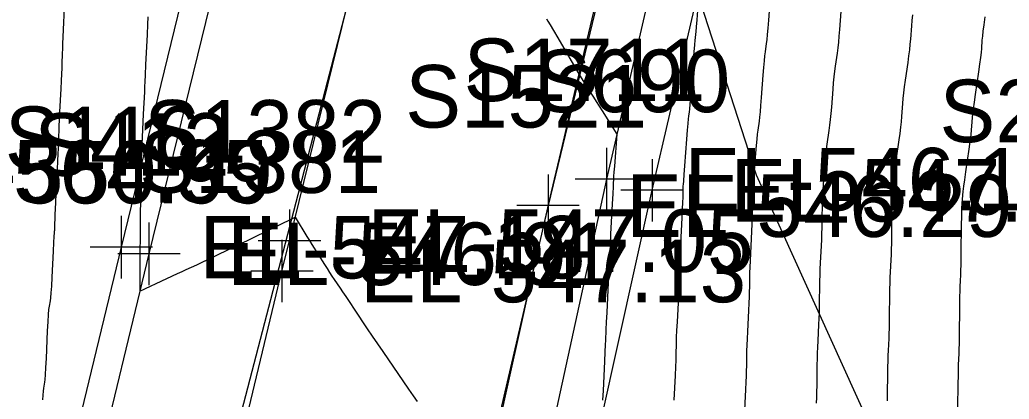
# Model space of a CAD drawing. Extents: x 1724534 to 1727318, y 657156 to 660047.
# Drawn here: x 1725468.1 to 1725531.4, y 659119.9 to 659144.2 of the extents above; entities that cross this region are included whole.
import ezdxf

# ---------------------------------------------------------------- set-up
doc = ezdxf.new("R2010")
doc.units = 0
for name, color, linetype in [('SURVEY - CENTERLINE - Preliminary', 7, 'Continuous'), ('SURVEY - CONTOURS - Index with Text', 7, 'Continuous'), ('SURVEY - CONTOURS - Intermediate with optional Text', 7, 'Continuous'), ('SURVEY - DRAINAGE - Area Shapes', 7, 'Continuous'), ('SURVEY - DTM - Breaklines', 7, 'Continuous'), ('SURVEY - DTM - Breaklines - Points - Elevations', 7, 'Continuous'), ('SURVEY - DTM - Breaklines - Points - Locators', 7, 'Continuous'), ('SURVEY - DTM - Breaklines - Points - Numbers', 7, 'Continuous'), ('SURVEY - NON-TRANSPORTATION - Features - Points - Elevations', 7, 'Continuous'), ('SURVEY - ROADSIDE BARRIERS - Points - Elevations', 7, 'Continuous'), ('SURVEY - ROADSIDE BARRIERS - Points - Locators', 7, 'Continuous'), ('SURVEY - ROADSIDE BARRIERS - Points - Numbers', 7, 'Continuous'), ('SURVEY - ROADSIDE BARRIERS with Text', 7, 'Continuous'), ('SURVEY - TRANSPORTATION - Features', 7, 'Continuous'), ('SURVEY - TRANSPORTATION - Features - Points - Elevations', 7, 'Continuous'), ('SURVEY - TRANSPORTATION - Features - Points - Locators', 7, 'Continuous'), ('SURVEY - TRANSPORTATION - Features - Points - Numbers', 7, 'Continuous'), ('SURVEY - TRANSPORTATION - Roads', 7, 'Continuous'), ('SURVEY - TRANSPORTATION - Roads - Points - Elevations', 7, 'Continuous'), ('SURVEY - TRANSPORTATION - Roads - Points - Locators', 7, 'Continuous'), ('SURVEY - TRANSPORTATION - Roads - Points - Numbers', 7, 'Continuous'), ('SURVEY - UTILITIES - Fiber Optic Cable (Underground) with Text', 7, 'Continuous')]:
    doc.layers.add(name, color=color, linetype=linetype)

msp = doc.modelspace()

# ---------------------------------------------------------------- linework, layer by layer
at = {"layer": 'SURVEY - CENTERLINE - Preliminary'}
msp.add_arc((1727061.077, 658773.081), 1600, 165.79242, 172.785391, dxfattribs=at)
msp.add_arc((1727061.077, 658773.081), 1600, 165.79242, 172.785391, dxfattribs=at)
msp.add_arc((1727061.077, 658773.081), 1600, 165.79242, 172.785391, dxfattribs=at)
at = {"layer": 'SURVEY - CONTOURS - Index with Text'}
msp.add_lwpolyline([(1725511.471, 659144.759), (1725511.426, 659144.162), (1725511.391, 659143.71), (1725511.365, 659143.405), (1725511.348, 659143.245), (1725511.315, 659143.013), (1725511.297, 659142.856), (1725511.271, 659142.557), (1725511.236, 659142.116), (1725511.192, 659141.533), (1725511.062, 659139.79), (1725511.018, 659139.206), (1725510.982, 659138.759), (1725510.954, 659138.449), (1725510.935, 659138.278), (1725510.895, 659138.003), (1725510.876, 659137.834), (1725510.849, 659137.53), (1725510.813, 659137.093), (1725510.769, 659136.523), (1725510.639, 659134.823), (1725510.596, 659134.265), (1725510.566, 659133.866), (1725510.548, 659133.627), (1725510.542, 659133.547), (1725510.542, 659133.547), (1725510.542, 659133.547), (1725510.542, 659133.547), (1725510.542, 659133.547), (1725510.542, 659133.546), (1725510.542, 659133.546), (1725510.541, 659133.531), (1725510.541, 659133.485), (1725510.54, 659133.41), (1725510.539, 659133.304), (1725510.535, 659132.982), (1725510.53, 659132.799), (1725510.517, 659132.49), (1725510.496, 659132.055), (1725510.468, 659131.494), (1725510.382, 659129.831), (1725510.353, 659129.268), (1725510.333, 659128.826), (1725510.32, 659128.506), (1725510.314, 659128.308), (1725510.31, 659127.941), (1725510.305, 659127.744), (1725510.292, 659127.431), (1725510.273, 659127), (1725510.245, 659126.451), (1725510.163, 659124.832), (1725510.136, 659124.282), (1725510.116, 659123.845), (1725510.104, 659123.521), (1725510.099, 659123.31), (1725510.094, 659122.9), (1725510.089, 659122.691), (1725510.077, 659122.373), (1725510.058, 659121.946), (1725510.032, 659121.409), (1725509.954, 659119.833)], dxfattribs=at)
at = {"layer": 'SURVEY - CONTOURS - Intermediate with optional Text'}
for points in [[(1725516.116, 659145.627), (1725516.008, 659144.15), (1725515.969, 659143.641), (1725515.933, 659143.22), (1725515.9, 659142.887), (1725515.87, 659142.642), (1725515.793, 659142.107), (1725515.762, 659141.864), (1725515.729, 659141.536), (1725515.693, 659141.124), (1725515.654, 659140.626), (1725515.547, 659139.185), (1725515.508, 659138.686), (1725515.471, 659138.268), (1725515.437, 659137.932), (1725515.405, 659137.678), (1725515.323, 659137.109), (1725515.291, 659136.857), (1725515.256, 659136.526), (1725515.22, 659136.116), (1725515.181, 659135.628), (1725515.073, 659134.221), (1725515.013, 659133.429), (1725514.998, 659133.231), (1725514.993, 659133.164), (1725514.993, 659133.164), (1725514.993, 659133.164), (1725514.993, 659133.163), (1725514.993, 659133.134), (1725514.992, 659133.048), (1725514.987, 659132.702), (1725514.98, 659132.088), (1725514.975, 659131.822), (1725514.963, 659131.485), (1725514.945, 659131.077), (1725514.851, 659129.223), (1725514.827, 659128.741), (1725514.809, 659128.327), (1725514.798, 659127.981), (1725514.792, 659127.702), (1725514.785, 659127.048), (1725514.779, 659126.771), (1725514.768, 659126.43), (1725514.751, 659126.025), (1725514.728, 659125.556), (1725514.661, 659124.221), (1725514.638, 659123.75), (1725514.621, 659123.34), (1725514.61, 659122.99), (1725514.604, 659122.7), (1725514.597, 659122.008), (1725514.591, 659121.72), (1725514.58, 659121.376), (1725514.564, 659120.974), (1725514.542, 659120.516), (1725514.456, 659118.758)], [(1725470.975, 659144.912), (1725470.909, 659143.545), (1725470.887, 659143.065), (1725470.868, 659142.651), (1725470.854, 659142.302), (1725470.843, 659142.02), (1725470.822, 659141.354), (1725470.811, 659141.067), (1725470.796, 659140.704), (1725470.776, 659140.266), (1725470.751, 659139.752), (1725470.68, 659138.283), (1725470.655, 659137.774), (1725470.636, 659137.35), (1725470.621, 659137.012), (1725470.612, 659136.758), (1725470.593, 659136.196), (1725470.583, 659135.937), (1725470.567, 659135.585), (1725470.547, 659135.137), (1725470.52, 659134.595), (1725470.442, 659133.024), (1725470.416, 659132.487), (1725470.395, 659132.054), (1725470.381, 659131.725), (1725470.372, 659131.5), (1725470.356, 659131.04), (1725470.351, 659130.888), (1725470.347, 659130.777), (1725470.344, 659130.708), (1725470.343, 659130.679), (1725470.342, 659130.659), (1725470.342, 659130.651), (1725470.341, 659130.645), (1725470.341, 659130.639), (1725470.34, 659130.634), (1725470.337, 659130.621), (1725470.332, 659130.539), (1725470.32, 659130.301), (1725470.299, 659129.908), (1725470.271, 659129.36), (1725470.185, 659127.69), (1725470.153, 659127.126), (1725470.123, 659126.686), (1725470.095, 659126.37), (1725470.069, 659126.178), (1725470.001, 659125.831), (1725469.975, 659125.635), (1725469.948, 659125.306), (1725469.92, 659124.845), (1725469.891, 659124.252), (1725469.812, 659122.493), (1725469.783, 659121.904), (1725469.758, 659121.454), (1725469.735, 659121.146), (1725469.714, 659120.977), (1725469.663, 659120.714), (1725469.643, 659120.586), (1725469.622, 659120.398), (1725469.6, 659120.151), (1725469.578, 659119.844)], [(1725520.631, 659144.707), (1725520.546, 659143.542), (1725520.513, 659143.12), (1725520.476, 659142.729), (1725520.435, 659142.369), (1725520.392, 659142.039), (1725520.271, 659141.201), (1725520.227, 659140.873), (1725520.187, 659140.516), (1725520.15, 659140.131), (1725520.116, 659139.719), (1725520.031, 659138.58), (1725519.998, 659138.166), (1725519.96, 659137.778), (1725519.919, 659137.415), (1725519.874, 659137.079), (1725519.75, 659136.215), (1725519.705, 659135.88), (1725519.664, 659135.521), (1725519.627, 659135.138), (1725519.593, 659134.733), (1725519.508, 659133.619), (1725519.48, 659133.254), (1725519.46, 659132.993), (1725519.448, 659132.836), (1725519.444, 659132.783), (1725519.444, 659132.782), (1725519.444, 659132.782), (1725519.444, 659132.782), (1725519.444, 659132.782), (1725519.444, 659132.781), (1725519.444, 659132.781), (1725519.444, 659132.738), (1725519.442, 659132.611), (1725519.426, 659131.194), (1725519.42, 659130.846), (1725519.409, 659130.481), (1725519.395, 659130.099), (1725519.376, 659129.7), (1725519.32, 659128.615), (1725519.301, 659128.215), (1725519.286, 659127.829), (1725519.276, 659127.456), (1725519.27, 659127.096), (1725519.259, 659126.155), (1725519.253, 659125.797), (1725519.243, 659125.429), (1725519.229, 659125.05), (1725519.211, 659124.661), (1725519.158, 659123.61), (1725519.14, 659123.219), (1725519.126, 659122.835), (1725519.116, 659122.459), (1725519.11, 659122.091), (1725519.099, 659121.117), (1725519.093, 659120.75), (1725519.084, 659120.378), (1725519.07, 659120.002), (1725519.053, 659119.622)], [(1725476.327, 659144.354), (1725476.304, 659143.872), (1725476.273, 659143.228), (1725476.181, 659141.294), (1725476.15, 659140.654), (1725476.128, 659140.187), (1725476.114, 659139.893), (1725476.108, 659139.77), (1725476.105, 659139.674), (1725476.1, 659139.551), (1725476.031, 659138.136), (1725475.864, 659134.715), (1725475.864, 659134.617), (1725475.863, 659134.601), (1725475.863, 659134.588), (1725475.863, 659134.576), (1725475.863, 659134.546), (1725475.862, 659134.479), (1725475.861, 659134.3), (1725475.858, 659134.009), (1725475.855, 659133.607), (1725475.844, 659132.386), (1725475.84, 659131.946), (1725475.83, 659130.846), (1725475.822, 659130.013), (1725475.817, 659129.542), (1725475.816, 659129.421), (1725475.816, 659129.378), (1725475.816, 659129.363), (1725475.816, 659129.358), (1725475.816, 659129.353), (1725475.816, 659129.349), (1725475.816, 659129.345), (1725475.815, 659129.337), (1725475.815, 659129.286), (1725475.815, 659129.141), (1725475.815, 659126.79), (1725477.54, 659127.601), (1725478.22, 659127.92), (1725478.516, 659128.059), (1725478.782, 659128.183), (1725479.452, 659128.495), (1725479.673, 659128.598), (1725479.833, 659128.672), (1725479.932, 659128.718), (1725479.97, 659128.736), (1725479.99, 659128.746), (1725480.035, 659128.768), (1725480.155, 659128.825), (1725481.44, 659129.443), (1725481.746, 659129.59), (1725482.356, 659129.884), (1725482.658, 659130.03), (1725483.464, 659130.419), (1725483.759, 659130.562), (1725484.042, 659130.7), (1725484.312, 659130.831), (1725484.57, 659130.956), (1725485.741, 659131.527), (1725486.491, 659130.307), (1725486.653, 659130.044), (1725486.818, 659129.778), (1725487.614, 659128.504), (1725487.782, 659128.239), (1725487.942, 659127.99), (1725488.094, 659127.759), (1725488.239, 659127.544), (1725488.614, 659126.996), (1725488.776, 659126.757), (1725488.98, 659126.453), (1725489.228, 659126.082), (1725489.518, 659125.646), (1725490.35, 659124.395), (1725490.667, 659123.92), (1725490.997, 659123.431), (1725491.338, 659122.93), (1725492.988, 659120.533), (1725493.285, 659120.101), (1725493.539, 659119.727)], [(1725501.809, 659144.239), (1725501.898, 659144.09), (1725502.048, 659143.837), (1725502.258, 659143.48), (1725502.529, 659143.017), (1725503.931, 659140.616), (1725504.653, 659139.463), (1725504.814, 659139.207), (1725504.986, 659138.934), (1725505.171, 659138.643), (1725505.368, 659138.335), (1725506.313, 659136.854), (1725506.157, 659134.807), (1725506.128, 659134.423), (1725506.107, 659134.149), (1725506.094, 659133.984), (1725506.09, 659133.929), (1725506.09, 659133.929), (1725506.09, 659133.929), (1725506.09, 659133.929), (1725506.09, 659133.929), (1725506.09, 659133.929), (1725506.09, 659133.928), (1725506.09, 659133.927), (1725506.09, 659133.922), (1725506.09, 659133.915), (1725506.09, 659133.906), (1725506.09, 659133.877), (1725506.085, 659133.775), (1725506.07, 659133.494), (1725506.047, 659133.032), (1725506.014, 659132.39), (1725505.913, 659130.438), (1725505.88, 659129.794), (1725505.856, 659129.325), (1725505.841, 659129.032), (1725505.836, 659128.914), (1725505.836, 659128.833), (1725505.831, 659128.718), (1725505.817, 659128.432), (1725505.794, 659127.974), (1725505.763, 659127.346), (1725505.666, 659125.444), (1725505.635, 659124.814), (1725505.612, 659124.35), (1725505.598, 659124.052), (1725505.593, 659123.92), (1725505.591, 659123.791), (1725505.587, 659123.662), (1725505.573, 659123.37), (1725505.552, 659122.918), (1725505.521, 659122.303), (1725505.429, 659120.448), (1725505.399, 659119.832)], [(1725525.211, 659144.478), (1725525.174, 659144.12), (1725525.146, 659143.787), (1725525.084, 659142.933), (1725525.056, 659142.599), (1725525.018, 659142.239), (1725524.971, 659141.851), (1725524.914, 659141.437), (1725524.749, 659140.295), (1725524.692, 659139.881), (1725524.644, 659139.496), (1725524.607, 659139.139), (1725524.578, 659138.811), (1725524.516, 659137.975), (1725524.488, 659137.646), (1725524.45, 659137.287), (1725524.402, 659136.898), (1725524.344, 659136.479), (1725524.177, 659135.321), (1725524.119, 659134.903), (1725524.072, 659134.516), (1725524.033, 659134.161), (1725524.005, 659133.837), (1725523.943, 659133.017), (1725523.922, 659132.748), (1725523.907, 659132.556), (1725523.899, 659132.44), (1725523.896, 659132.401), (1725523.896, 659132.4), (1725523.896, 659132.4), (1725523.896, 659132.399), (1725523.896, 659132.399), (1725523.895, 659132.342), (1725523.89, 659131.892), (1725523.885, 659131.499), (1725523.871, 659130.3), (1725523.865, 659129.869), (1725523.856, 659129.476), (1725523.844, 659129.121), (1725523.83, 659128.804), (1725523.789, 659128.008), (1725523.775, 659127.689), (1725523.763, 659127.33), (1725523.754, 659126.93), (1725523.748, 659126.49), (1725523.734, 659125.263), (1725523.727, 659124.824), (1725523.719, 659124.428), (1725523.707, 659124.075), (1725523.694, 659123.766), (1725523.655, 659122.998), (1725523.642, 659122.687), (1725523.631, 659122.331), (1725523.622, 659121.929), (1725523.616, 659121.481), (1725523.602, 659120.226), (1725523.595, 659119.779)], [(1725529.846, 659144.351), (1725529.776, 659143.854), (1725529.722, 659143.441), (1725529.684, 659143.112), (1725529.661, 659142.867), (1725529.621, 659142.324), (1725529.599, 659142.079), (1725529.56, 659141.748), (1725529.506, 659141.333), (1725529.435, 659140.834), (1725529.227, 659139.389), (1725529.156, 659138.89), (1725529.102, 659138.476), (1725529.063, 659138.147), (1725529.04, 659137.904), (1725529.001, 659137.37), (1725528.978, 659137.126), (1725528.939, 659136.797), (1725528.884, 659136.381), (1725528.814, 659135.88), (1725528.604, 659134.427), (1725528.534, 659133.926), (1725528.479, 659133.511), (1725528.44, 659133.183), (1725528.417, 659132.942), (1725528.377, 659132.415), (1725528.354, 659132.119), (1725528.349, 659132.044), (1725528.347, 659132.019), (1725528.347, 659132.018), (1725528.347, 659132.017), (1725528.347, 659132.016), (1725528.347, 659132.016), (1725528.347, 659132.016), (1725528.346, 659131.946), (1725528.344, 659131.736), (1725528.334, 659130.897), (1725528.317, 659129.406), (1725528.31, 659128.892), (1725528.302, 659128.472), (1725528.293, 659128.143), (1725528.284, 659127.907), (1725528.258, 659127.4), (1725528.248, 659127.163), (1725528.24, 659126.831), (1725528.232, 659126.405), (1725528.225, 659125.884), (1725528.201, 659123.85), (1725528.194, 659123.427), (1725528.186, 659123.101), (1725528.177, 659122.871), (1725528.152, 659122.387), (1725528.144, 659122.156), (1725528.135, 659121.826), (1725528.128, 659121.398), (1725528.121, 659120.871), (1725528.104, 659119.335)]]:
    msp.add_lwpolyline(points, dxfattribs=at)
at = {"layer": 'SURVEY - DRAINAGE - Area Shapes'}
msp.add_lwpolyline([(1725457.865, 659006.777), (1725413.857, 659016.262), (1725297.605, 659050.843), (1725314.042, 659296.608), (1725386.76, 659493.901), (1725483.401, 659755.229), (1725623.949, 659732.704), (1725676.22, 659724.326), (1725634.82, 659466.017), (1725543.324, 659353.721), (1725499.683, 659185.923), (1725479.088, 659106.738)], close=True, dxfattribs=at)
at = {"layer": 'SURVEY - DTM - Breaklines'}
msp.add_lwpolyline([(1725504.884, 659250.966), (1725498.725, 659226.793), (1725492.704, 659202.503), (1725486.609, 659178.27), (1725480.544, 659153.955), (1725474.624, 659129.616), (1725468.741, 659105.278), (1725462.975, 659080.964), (1725457.482, 659056.509), (1725452.226, 659031.922), (1725447.641, 659009.959), (1725446.425, 659003.851), (1725441.811, 658979.15), (1725437.527, 658954.376), (1725432.503, 658922.481), (1725434.197, 658921.722)], dxfattribs=at)
at = {"layer": 'SURVEY - DTM - Breaklines - Points - Locators'}
for p, q in [((1725474.624, 659131.616), (1725474.624, 659127.616)), ((1725476.624, 659129.616), (1725472.624, 659129.616))]:
    msp.add_line(p, q, dxfattribs=at)
at = {"layer": 'SURVEY - ROADSIDE BARRIERS - Points - Locators'}
for p, q in [((1725508.576, 659135.257), (1725508.576, 659131.257)), ((1725510.576, 659133.257), (1725506.576, 659133.257))]:
    msp.add_line(p, q, dxfattribs=at)
at = {"layer": 'SURVEY - ROADSIDE BARRIERS with Text'}
msp.add_lwpolyline([(1725454.307, 658763.664), (1725456.988, 658788.398), (1725459.975, 658813.106), (1725462.961, 658837.817), (1725466.031, 658862.66), (1725469.198, 658887.437), (1725472.364, 658912.252), (1725475.489, 658936.998), (1725478.578, 658961.799), (1725481.795, 658986.471), (1725485.277, 659011.185), (1725489.239, 659035.685), (1725493.561, 659060.194), (1725498.271, 659084.816), (1725503.177, 659108.92), (1725508.576, 659133.257), (1725514.221, 659157.599), (1725521.221, 659181.564), (1725529.697, 659209.302)], dxfattribs=at)
at = {"layer": 'SURVEY - TRANSPORTATION - Features'}
for points in [[(1725537.281, 659258.937), (1725530.962, 659234.747), (1725524.817, 659210.531), (1725517.386, 659182.521), (1725511.279, 659158.31), (1725505.645, 659133.966), (1725500.348, 659109.577), (1725495.279, 659085.33), (1725490.855, 659060.693), (1725486.478, 659036.153), (1725482.443, 659011.591), (1725478.797, 658986.889), (1725475.825, 658962.14), (1725472.769, 658937.341)], [(1725506.673, 659250.514), (1725500.512, 659226.334), (1725494.493, 659202.049), (1725488.389, 659177.819), (1725482.327, 659153.516), (1725476.395, 659129.191), (1725470.514, 659104.862), (1725464.748, 659080.55), (1725459.259, 659056.109), (1725454.008, 659031.549), (1725449.429, 659009.612), (1725448.213, 659003.504), (1725443.603, 658978.829), (1725439.325, 658954.082), (1725434.304, 658922.209), (1725434.197, 658921.722)]]:
    msp.add_lwpolyline(points, dxfattribs=at)
at = {"layer": 'SURVEY - TRANSPORTATION - Features - Points - Locators'}
for p, q in [((1725505.645, 659135.966), (1725505.645, 659131.966)), ((1725507.645, 659133.966), (1725503.645, 659133.966)), ((1725476.395, 659131.191), (1725476.395, 659127.191)), ((1725478.395, 659129.191), (1725474.395, 659129.191))]:
    msp.add_line(p, q, dxfattribs=at)
at = {"layer": 'SURVEY - TRANSPORTATION - Roads'}
for points in [[(1725445.023, 658936.389), (1725447.926, 658954.139), (1725448.261, 658956.109), (1725453.558, 658985.616), (1725453.93, 658987.58), (1725458.117, 659009.159), (1725458.517, 659011.117), (1725466.292, 659048.286), (1725466.718, 659050.238), (1725471.114, 659069.737), (1725478.393, 659100.872), (1725479.306, 659104.764), (1725484.9, 659128.087), (1725485.373, 659130.029), (1725489.666, 659147.5), (1725494.922, 659168.852), (1725495.411, 659170.791), (1725504.745, 659207.606), (1725509.226, 659225.033), (1725509.717, 659226.971)], [(1725509.433, 659163.358), (1725501.913, 659132.272), (1725496.037, 659106.962), (1725495.616, 659105.008), (1725492.293, 659089.367), (1725491.93, 659087.402), (1725490.237, 659077.551), (1725489.888, 659075.583), (1725484.442, 659046.101), (1725484.106, 659044.131), (1725480.436, 659022.454), (1725480.115, 659020.482), (1725477.562, 659002.676), (1725474.526, 658980.901), (1725474.261, 658978.921), (1725472.804, 658967.02), (1725471.086, 658953.138), (1725470.348, 658947.189), (1725468.597, 658933.312)]]:
    msp.add_lwpolyline(points, dxfattribs=at)
at = {"layer": 'SURVEY - TRANSPORTATION - Roads - Points - Locators'}
for p, q in [((1725501.913, 659134.272), (1725501.913, 659130.272)), ((1725485.373, 659132.029), (1725485.373, 659128.029)), ((1725503.913, 659132.272), (1725499.913, 659132.272)), ((1725487.373, 659130.029), (1725483.373, 659130.029)), ((1725484.9, 659130.087), (1725484.9, 659126.087)), ((1725486.9, 659128.087), (1725482.9, 659128.087))]:
    msp.add_line(p, q, dxfattribs=at)
at = {"layer": 'SURVEY - UTILITIES - Fiber Optic Cable (Underground) with Text'}
msp.add_line((1725515.229, 659134.254), (1725533.816, 659093.214), dxfattribs=at)
msp.add_lwpolyline([(1725493.518, 659243.033), (1725493.322, 659242.827), (1725497.949, 659217.072), (1725500.753, 659198.279), (1725509.549, 659151.809), (1725515.229, 659134.254)], dxfattribs=at)

# ---------------------------------------------------------------- texts
at = {"layer": 'SURVEY - DTM - Breaklines - Points - Elevations'}
for s, p in [('EL-564.35', (1725459.379, 659132.473)), ('EL-547.18', (1725479.624, 659127.616))]:
    msp.add_text(s, height=4, dxfattribs=at).set_placement(p)
at = {"layer": 'SURVEY - DTM - Breaklines - Points - Numbers'}
for s, p in [('S2206', (1725526.948, 659136.334)), ('S116', (1725467.178, 659134.616))]:
    msp.add_text(s, height=4, dxfattribs=at).set_placement(p)
at = {"layer": 'SURVEY - NON-TRANSPORTATION - Features - Points - Elevations'}
msp.add_text('EL-550.99', height=4, dxfattribs=at).set_placement((1725459.62, 659132.415))
at = {"layer": 'SURVEY - ROADSIDE BARRIERS - Points - Elevations'}
msp.add_text('EL-547.89', height=4, dxfattribs=at).set_placement((1725513.576, 659131.257))
at = {"layer": 'SURVEY - ROADSIDE BARRIERS - Points - Numbers'}
msp.add_text('S690', height=4, dxfattribs=at).set_placement((1725501.067, 659138.257))
at = {"layer": 'SURVEY - TRANSPORTATION - Features - Points - Elevations'}
for s, p in [('EL-546.10', (1725510.645, 659131.966)), ('EL-546.91', (1725481.395, 659127.191))]:
    msp.add_text(s, height=4, dxfattribs=at).set_placement(p)
at = {"layer": 'SURVEY - TRANSPORTATION - Features - Points - Numbers'}
for s, p in [('S1711', (1725496.515, 659138.966)), ('S412', (1725469.059, 659134.191))]:
    msp.add_text(s, height=4, dxfattribs=at).set_placement(p)
at = {"layer": 'SURVEY - TRANSPORTATION - Roads - Points - Elevations'}
for s, p in [('EL-546.29', (1725506.913, 659130.272)), ('EL-547.05', (1725490.373, 659128.029)), ('EL-547.13', (1725489.9, 659126.087))]:
    msp.add_text(s, height=4, dxfattribs=at).set_placement(p)
at = {"layer": 'SURVEY - TRANSPORTATION - Roads - Points - Numbers'}
for s, p in [('S1521', (1725492.783, 659137.272)), ('S1382', (1725476.085, 659135.029)), ('S1381', (1725475.77, 659133.087))]:
    msp.add_text(s, height=4, dxfattribs=at).set_placement(p)

doc.saveas('drawing.dxf')
